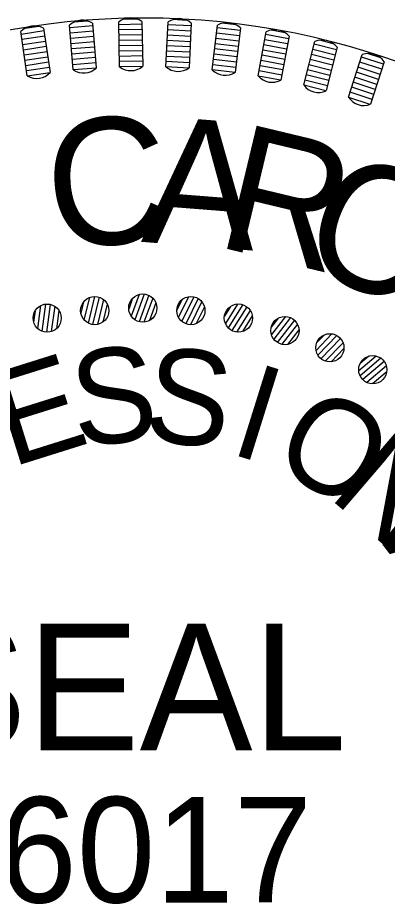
# Model space of a CAD drawing. Extents: x 2111095 to 2115970, y 670428 to 672393.
# Drawn here: x 2113194.31 to 2113212.15, y 672102.32 to 672145.09 of the extents above; entities that cross this region are included whole.
import ezdxf

# ---------------------------------------------------------------- set-up
doc = ezdxf.new("R2010")
doc.units = 0
doc.layers.add('Sheet PE Seal Cell', color=7, linetype='Continuous')

msp = doc.modelspace()

# ---------------------------------------------------------------- linework, layer by layer
at = {"layer": 'Sheet PE Seal Cell'}
for p, q in [((2113200.086, 672145.027), (2113199.407, 672145.015)), ((2113202.476, 672144.965), (2113201.797, 672144.999)), ((2113195.321, 672144.676), (2113194.648, 672144.575)), ((2113195.555, 672144.586), (2113195.875, 672142.452)), ((2113196.992, 672142.582), (2113196.813, 672144.733)), ((2113197.936, 672144.694), (2113196.824, 672144.602)), ((2113197.698, 672144.93), (2113197.02, 672144.874)), ((2113197.925, 672144.825), (2113198.104, 672142.675)), ((2113199.227, 672142.731), (2113199.191, 672144.888)), ((2113200.309, 672144.776), (2113199.193, 672144.757)), ((2113200.313, 672144.521), (2113199.197, 672144.502)), ((2113200.307, 672144.907), (2113200.343, 672142.749)), ((2113201.467, 672142.731), (2113201.573, 672144.886)), ((2113202.682, 672144.7), (2113201.567, 672144.755)), ((2113202.688, 672144.831), (2113202.582, 672142.676)), ((2113203.702, 672142.583), (2113203.95, 672144.727)), ((2113205.044, 672144.468), (2113203.935, 672144.597)), ((2113204.857, 672144.746), (2113204.181, 672144.824)), ((2113205.059, 672144.598), (2113204.811, 672142.455)), ((2113194.772, 672142.286), (2113194.451, 672144.42)), ((2113195.574, 672144.456), (2113194.471, 672144.29)), ((2113195.612, 672144.204), (2113194.508, 672144.038)), ((2113197.957, 672144.44), (2113196.845, 672144.348)), ((2113197.979, 672144.187), (2113196.866, 672144.094)), ((2113200.317, 672144.266), (2113199.201, 672144.248)), ((2113202.656, 672144.191), (2113201.542, 672144.246)), ((2113202.669, 672144.446), (2113201.554, 672144.501)), ((2113204.985, 672143.962), (2113203.877, 672144.09)), ((2113205.015, 672144.215), (2113203.906, 672144.343)), ((2113205.922, 672142.288), (2113206.312, 672144.411)), ((2113207.386, 672144.08), (2113206.288, 672144.282)), ((2113207.218, 672144.37), (2113206.549, 672144.493)), ((2113207.41, 672144.209), (2113207.02, 672142.087)), ((2113195.65, 672143.952), (2113194.546, 672143.787)), ((2113195.688, 672143.7), (2113194.584, 672143.535)), ((2113198, 672143.933), (2113196.887, 672143.84)), ((2113198.021, 672143.679), (2113196.908, 672143.586)), ((2113200.322, 672144.012), (2113199.206, 672143.993)), ((2113200.326, 672143.757), (2113199.21, 672143.738)), ((2113202.631, 672143.682), (2113201.516, 672143.737)), ((2113202.644, 672143.937), (2113201.529, 672143.992)), ((2113204.956, 672143.709), (2113203.847, 672143.837)), ((2113207.294, 672143.579), (2113206.196, 672143.781)), ((2113207.34, 672143.83), (2113206.242, 672144.031)), ((2113208.118, 672141.847), (2113208.647, 672143.94)), ((2113209.697, 672143.538), (2113208.615, 672143.812)), ((2113209.548, 672143.839), (2113208.889, 672144.005)), ((2113209.73, 672143.666), (2113209.2, 672141.574)), ((2113195.726, 672143.449), (2113194.622, 672143.283)), ((2113198.042, 672143.425), (2113196.929, 672143.333)), ((2113200.33, 672143.502), (2113199.214, 672143.483)), ((2113200.335, 672143.247), (2113199.218, 672143.229)), ((2113202.619, 672143.428), (2113201.504, 672143.483)), ((2113204.897, 672143.203), (2113203.788, 672143.331)), ((2113204.927, 672143.456), (2113203.818, 672143.584)), ((2113207.202, 672143.078), (2113206.104, 672143.28)), ((2113207.248, 672143.328), (2113206.15, 672143.53)), ((2113209.572, 672143.044), (2113208.49, 672143.318)), ((2113209.635, 672143.291), (2113208.553, 672143.565)), ((2113210.28, 672141.262), (2113210.947, 672143.315)), ((2113211.839, 672143.155), (2113211.192, 672143.365)), ((2113195.764, 672143.197), (2113194.66, 672143.031)), ((2113195.801, 672142.945), (2113194.698, 672142.779)), ((2113198.063, 672143.171), (2113196.951, 672143.079)), ((2113198.084, 672142.917), (2113196.972, 672142.825)), ((2113200.339, 672142.993), (2113199.223, 672142.974)), ((2113202.594, 672142.919), (2113201.479, 672142.974)), ((2113202.606, 672143.174), (2113201.491, 672143.229)), ((2113204.839, 672142.697), (2113203.73, 672142.825)), ((2113204.868, 672142.95), (2113203.759, 672143.078)), ((2113207.156, 672142.827), (2113206.058, 672143.029)), ((2113209.447, 672142.55), (2113208.365, 672142.824)), ((2113209.51, 672142.797), (2113208.428, 672143.071)), ((2113211.889, 672142.603), (2113210.827, 672142.947)), ((2113211.968, 672142.845), (2113210.906, 672143.19)), ((2113212.008, 672142.97), (2113211.342, 672140.917)), ((2113195.839, 672142.693), (2113194.735, 672142.527)), ((2113195.863, 672142.439), (2113194.787, 672142.277)), ((2113198.091, 672142.662), (2113197.007, 672142.572)), ((2113200.329, 672142.738), (2113199.241, 672142.72)), ((2113202.567, 672142.665), (2113201.48, 672142.719)), ((2113204.796, 672142.445), (2113203.714, 672142.571)), ((2113207.064, 672142.326), (2113205.966, 672142.528)), ((2113207.11, 672142.577), (2113206.012, 672142.778)), ((2113209.385, 672142.304), (2113208.303, 672142.577)), ((2113211.732, 672142.118), (2113210.67, 672142.463)), ((2113211.81, 672142.36), (2113210.749, 672142.705)), ((2113207.004, 672142.078), (2113205.934, 672142.275)), ((2113209.26, 672141.81), (2113208.178, 672142.083)), ((2113209.323, 672142.057), (2113208.24, 672142.33)), ((2113211.574, 672141.634), (2113210.513, 672141.978)), ((2113211.653, 672141.876), (2113210.591, 672142.221)), ((2113209.184, 672141.566), (2113208.129, 672141.833)), ((2113211.496, 672141.391), (2113210.434, 672141.736)), ((2113211.325, 672140.911), (2113210.29, 672141.247)), ((2113211.417, 672141.149), (2113210.355, 672141.494)), ((2113200.165, 672131.741), (2113199.786, 672130.7)), ((2113200.414, 672131.763), (2113199.964, 672130.524)), ((2113200.634, 672131.703), (2113200.17, 672130.428)), ((2113195.655, 672131.275), (2113195.471, 672129.969)), ((2113195.882, 672131.262), (2113195.693, 672129.919)), ((2113197.488, 672131.38), (2113197.356, 672130.847)), ((2113197.776, 672131.596), (2113197.508, 672130.522)), ((2113198.022, 672131.644), (2113197.703, 672130.364)), ((2113198.246, 672131.607), (2113197.919, 672130.291)), ((2113198.452, 672131.494), (2113198.153, 672130.294)), ((2113198.631, 672131.275), (2113198.414, 672130.404)), ((2113199.856, 672131.556), (2113199.669, 672131.04)), ((2113200.827, 672131.569), (2113200.404, 672130.407)), ((2113200.982, 672131.332), (2113200.675, 672130.489)), ((2113202.23, 672131.484), (2113201.989, 672130.99)), ((2113202.556, 672131.635), (2113202.071, 672130.64)), ((2113202.806, 672131.631), (2113202.228, 672130.446)), ((2113203.018, 672131.548), (2113202.424, 672130.329)), ((2113203.196, 672131.395), (2113202.654, 672130.284)), ((2113204.923, 672131.28), (2113204.336, 672130.341)), ((2113195.152, 672130.957), (2113195.076, 672130.413)), ((2113195.415, 672131.202), (2113195.261, 672130.106)), ((2113196.098, 672131.171), (2113195.926, 672129.947)), ((2113196.299, 672130.972), (2113196.175, 672130.083)), ((2113203.326, 672131.144), (2113202.932, 672130.337)), ((2113204.583, 672131.164), (2113204.292, 672130.698)), ((2113205.171, 672131.25), (2113204.473, 672130.131)), ((2113205.374, 672131.146), (2113204.655, 672129.995)), ((2113205.534, 672130.975), (2113204.879, 672129.926)), ((2113205.637, 672130.711), (2113205.162, 672129.949)), ((2113206.889, 672130.6), (2113206.551, 672130.167)), ((2113207.24, 672130.68), (2113206.558, 672129.807)), ((2113207.483, 672130.624), (2113206.672, 672129.584)), ((2113207.674, 672130.499), (2113206.839, 672129.43)), ((2113207.816, 672130.312), (2113207.055, 672129.338)), ((2113207.89, 672130.039), (2113207.338, 672129.331)), ((2113209.481, 672129.841), (2113208.712, 672129.044)), ((2113209.124, 672129.798), (2113208.743, 672129.402)), ((2113209.718, 672129.759), (2113208.802, 672128.811)), ((2113209.894, 672129.615), (2113208.952, 672128.639)), ((2113210.016, 672129.415), (2113209.157, 672128.525)), ((2113210.061, 672129.135), (2113209.438, 672128.489)), ((2113211.622, 672128.772), (2113210.774, 672128.06)), ((2113211.263, 672128.766), (2113210.842, 672128.413)), ((2113211.849, 672128.666), (2113210.839, 672127.818)), ((2113212.009, 672128.504), (2113210.971, 672127.632)), ((2113212.109, 672128.292), (2113211.163, 672127.497)), ((2113212.126, 672128.009), (2113211.438, 672127.432))]:
    msp.add_line(p, q, dxfattribs=at)
for centre, radius in [((2113200.402, 672108.877), 36.215), ((2113200.348, 672131.085), 0.681), ((2113195.73, 672130.599), 0.681), ((2113198.026, 672130.963), 0.681), ((2113202.669, 672130.964), 0.681), ((2113204.965, 672130.601), 0.681), ((2113207.211, 672130), 0.681), ((2113209.381, 672129.168), 0.681), ((2113211.453, 672128.113), 0.681)]:
    msp.add_circle(centre, radius, dxfattribs=at)
for centre, radius, start, end in [((2113197.43, 672144.048), 0.922, 57.4806, 132.0216), ((2113199.761, 672144.164), 0.922, 53.6912, 128.2321), ((2113202.094, 672144.126), 0.922, 49.9017, 124.4427), ((2113195.112, 672143.778), 0.922, 61.2701, 135.8111), ((2113204.42, 672143.934), 0.922, 46.1122, 120.6532), ((2113206.728, 672143.589), 0.922, 42.3228, 116.8637), ((2113209.009, 672143.092), 0.922, 38.5333, 113.0742), ((2113211.251, 672142.445), 0.922, 34.7438, 109.2848), ((2113195.223, 672143.039), 0.878, 239.0439, 318.0374), ((2113197.492, 672143.303), 0.878, 235.2544, 314.2479), ((2113199.773, 672143.417), 0.878, 231.4649, 310.4584), ((2113202.058, 672143.38), 0.878, 227.6754, 306.6689), ((2113204.334, 672143.192), 0.878, 223.886, 302.8795), ((2113206.593, 672142.854), 0.878, 220.0965, 299.09), ((2113208.825, 672142.367), 0.878, 216.307, 295.3005), ((2113211.02, 672141.734), 0.878, 212.5175, 291.511)]:
    msp.add_arc(centre, radius, start, end, dxfattribs=at)

# ---------------------------------------------------------------- texts
for s, height, rotation, p in [('C', 6.113, 4.5143, (2113195.923, 672133.926)), ('A', 6.113, 355.5143, (2113200.244, 672134.283)), ('R', 6.113, 346.5143, (2113203.767, 672134.096)), ('O', 6.113, 337.5143, (2113207.67, 672133.252)), ('S', 4.585, 5.8207, (2113197.127, 672124.382)), ('S', 4.585, 354.2078, (2113200.314, 672124.714)), ('E', 4.585, 17.4336, (2113193.993, 672123.391)), ('I', 4.585, 342.5949, (2113204.44, 672124.104)), ('O', 4.585, 330.982, (2113206.42, 672123.526)), ('N', 4.585, 319.3691, (2113209.244, 672122.005)), ('A', 4.585, 307.7562, (2113211.906, 672119.687)), ('SEAL', 6.1134, 0.0143, (2113189.291, 672109.74)), ('046017', 5.0945, 0.0143, (2113185.799, 672102.403))]:
    msp.add_text(s, height=height, rotation=rotation, dxfattribs=at).set_placement(p)

doc.saveas('drawing.dxf')
